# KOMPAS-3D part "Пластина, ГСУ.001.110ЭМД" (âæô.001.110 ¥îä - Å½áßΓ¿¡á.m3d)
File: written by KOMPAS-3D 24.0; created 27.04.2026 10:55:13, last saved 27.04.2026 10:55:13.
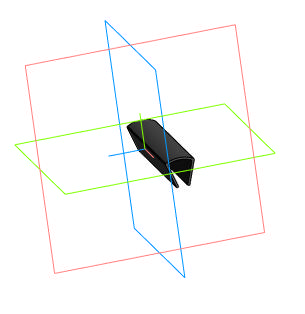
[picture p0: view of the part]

Document properties: Автор: USG_411; Полное имя файла: C:\Users\USG_411\Desktop\ГМ2704_411-15\Двигатель мясорубки\ГСУ.001.110 ЭМД - Пластина.m3d

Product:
- Part/product: Пластина  | designation ГСУ.001.110ЭМД
    Масса: 0.002837

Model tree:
1. Эскиз:1
2. Элемент выдавливания:1
     Толщина стенки 1 = 0.5; Расстояние 1 = 38
3. Скругление:1  (with: Ребро.Элемент выдавливания:1)
     Радиус = 0.3

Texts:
  ГСУ.001.110
  ГСУ.001.110 ЭМД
